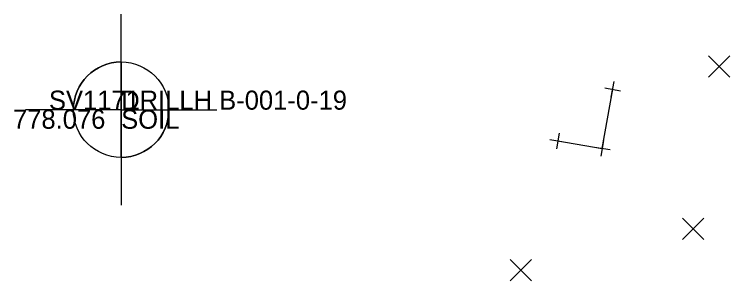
# Model space of a CAD drawing. Extents: x 1543088 to 1543675, y 586989 to 588001.
# Drawn here: x 1543087.99 to 1543132.92, y 587328.49 to 587345.25 of the extents above; entities that cross this region are included whole.
import ezdxf

# ---------------------------------------------------------------- set-up
doc = ezdxf.new("R2010")
doc.units = 0
for name, color, linetype in [('GT_Project_Soil_Boring', 7, 'Continuous'), ('SV_X_Break_Lines', 7, 'Continuous'), ('SV_X_Random_Point', 7, 'Continuous'), ('SV_X_Shot_Marker', 7, 'Continuous'), ('SV_X_Text_Comment', 7, 'Continuous'), ('SV_X_Text_Description', 7, 'Continuous'), ('SV_X_Text_Elevation', 7, 'Continuous'), ('SV_X_Text_Name', 7, 'Continuous')]:
    doc.layers.add(name, color=color, linetype=linetype)

msp = doc.modelspace()

# ---------------------------------------------------------------- linework, layer by layer
at = {"layer": 'GT_Project_Soil_Boring'}
for p, q in [((1543094.703, 587339.247), (1543094.703, 587345.247)), ((1543094.703, 587342.247), (1543094.703, 587339.247)), ((1543094.703, 587339.247), (1543088.703, 587339.247)), ((1543094.703, 587339.247), (1543091.703, 587339.247)), ((1543094.703, 587339.247), (1543094.703, 587333.247)), ((1543094.703, 587339.247), (1543100.703, 587339.247)), ((1543094.703, 587336.247), (1543094.703, 587339.247)), ((1543094.703, 587339.247), (1543097.703, 587339.247))]:
    msp.add_line(p, q, dxfattribs=at)
msp.add_circle((1543094.703, 587339.247), 3, dxfattribs=at)
for start, end in [(90, 180), (270, 360)]:
    msp.add_arc((1543094.703, 587339.247), 3, start, end, dxfattribs=at)
at = {"layer": 'SV_X_Break_Lines'}
msp.add_lwpolyline([(1543122.119, 587337.279), (1543124.912, 587336.815), (1543125.568, 587340.529)], dxfattribs=at)
at = {"layer": 'SV_X_Random_Point'}
for p, q in [((1543131.582, 587341.302), (1543132.916, 587342.637)), ((1543131.582, 587342.637), (1543132.916, 587341.302)), ((1543129.957, 587331.087), (1543131.291, 587332.422)), ((1543129.957, 587332.422), (1543131.291, 587331.087)), ((1543119.127, 587328.49), (1543120.461, 587329.825)), ((1543119.127, 587329.825), (1543120.461, 587328.49))]:
    msp.add_line(p, q, dxfattribs=at)
at = {"layer": 'SV_X_Shot_Marker'}
for p, q in [((1543125.481, 587340.037), (1543125.655, 587341.021)), ((1543125.076, 587340.616), (1543126.06, 587340.442)), ((1543125.568, 587340.529), (1543125.568, 587340.529)), ((1543122.201, 587337.772), (1543122.037, 587336.786)), ((1543121.626, 587337.361), (1543122.612, 587337.197)), ((1543122.119, 587337.279), (1543122.119, 587337.279)), ((1543124.994, 587337.308), (1543124.83, 587336.322)), ((1543124.419, 587336.897), (1543125.405, 587336.733)), ((1543124.912, 587336.815), (1543124.912, 587336.815))]:
    msp.add_line(p, q, dxfattribs=at)

# ---------------------------------------------------------------- texts
at = {"layer": 'SV_X_Text_Comment'}
msp.add_text('SOIL', height=1.2, dxfattribs=at).set_placement((1543094.703, 587338.047))
at = {"layer": 'SV_X_Text_Description'}
msp.add_text('DRILLH B-001-0-19', height=1.2, dxfattribs=at).set_placement((1543094.703, 587339.247))
at = {"layer": 'SV_X_Text_Elevation'}
msp.add_text('778.076', height=1.2, dxfattribs=at).set_placement((1543087.91, 587338.047))
at = {"layer": 'SV_X_Text_Name'}
msp.add_text('SV1171', height=1.2, dxfattribs=at).set_placement((1543090.167, 587339.247))

doc.saveas('drawing.dxf')
